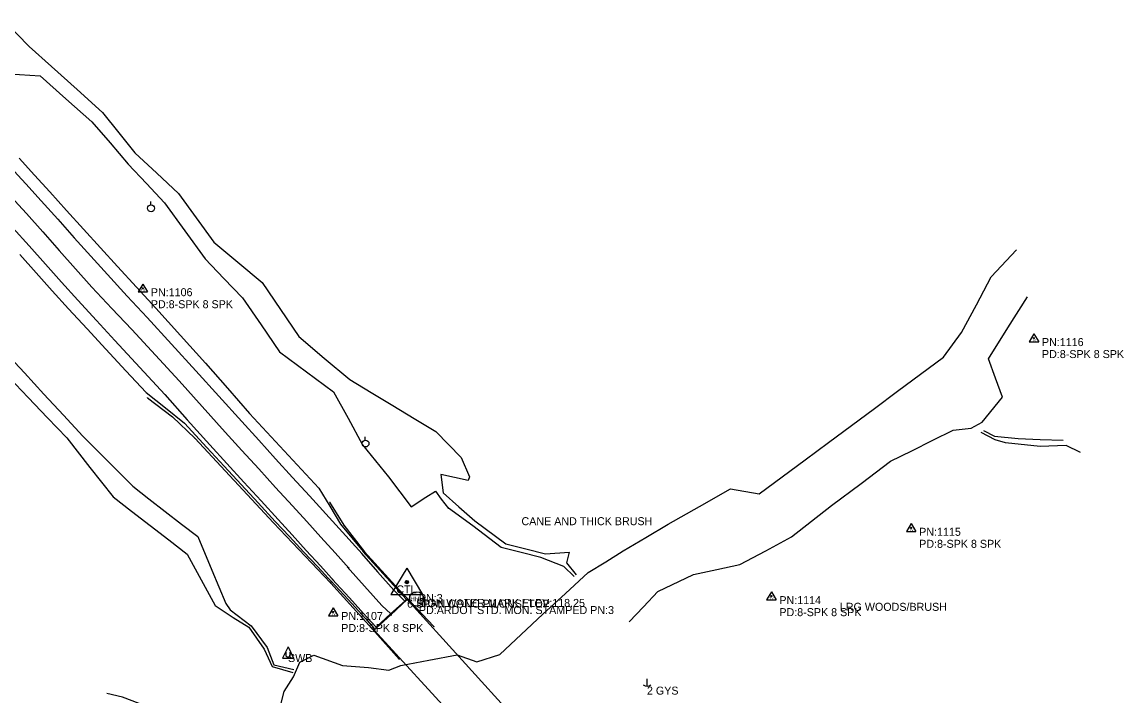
# Model space of a CAD drawing. Extents: x 1193883 to 1197064, y 1474583 to 1477379.
# Drawn here: x 1195271 to 1195959, y 1476046 to 1476468 of the extents above; entities that cross this region are included whole.
import ezdxf

# ---------------------------------------------------------------- set-up
doc = ezdxf.new("R2010")
doc.units = 0
for name, color, linetype in [('S_BRIDGE', 7, 'Continuous'), ('S_BRIDGE_ANNOT', 7, 'Continuous'), ('S_DITCHLINE', 7, 'Continuous'), ('S_EDGE_PAVEMENT', 7, 'Continuous'), ('S_GUARDRAIL', 7, 'Continuous'), ('S_HIST_HIGH_WATER', 7, 'Continuous'), ('S_HIST_HIGH_WATER_ANNOT', 7, 'Continuous'), ('S_MSC_PT_SYM', 7, 'Continuous'), ('S_PAVEMENT_CROWN', 7, 'Continuous'), ('S_PRIMARY_CTL', 7, 'Continuous'), ('S_PRIMARY_CTL_ANNOT', 7, 'Continuous'), ('S_RDW_PT_SYM', 7, 'Continuous'), ('S_SECONDARY_CTL', 7, 'Continuous'), ('S_SECONDARY_CTL_ANNOT', 7, 'Continuous'), ('S_SHOULDER', 7, 'Continuous'), ('S_STR_PT_SYM', 7, 'Continuous'), ('S_STREAM', 7, 'Continuous'), ('S_SURVEY_TEXT_ANNOT', 7, 'Continuous'), ('S_UTILITY_POLE', 7, 'Continuous'), ('S_UTILITY_POLE_ANNOT', 7, 'Continuous')]:
    doc.layers.add(name, color=color, linetype=linetype)

msp = doc.modelspace()

# ---------------------------------------------------------------- linework, layer by layer
at = {"layer": 'S_BRIDGE'}
for p, q in [((1195511.19, 1476106.62), (1195501.07, 1476097.22)), ((1195612.13, 1475995.59), (1195511.19, 1476106.62)), ((1195501.07, 1476097.22), (1195492.02, 1476089.1)), ((1195492.02, 1476089.1), (1195490.61, 1476087.6)), ((1195490.61, 1476087.6), (1195591.91, 1475977.01))]:
    msp.add_line(p, q, dxfattribs=at)
at = {"layer": 'S_DITCHLINE'}
for points in [[(1195260.5, 1476467.51), (1195275.09, 1476452.23), (1195289.07, 1476439.71), (1195305.06, 1476425.33), (1195321.05, 1476410.94), (1195331.13, 1476398.38), (1195341.21, 1476385.82), (1195354.85, 1476373.13), (1195368.49, 1476360.44), (1195379.47, 1476345.25), (1195390.46, 1476330.07), (1195405.56, 1476317.43), (1195420.66, 1476304.79), (1195432.12, 1476287.86), (1195443.59, 1476270.93), (1195459.5, 1476257.55), (1195475.4, 1476244.18), (1195488.82, 1476236.03), (1195502.24, 1476227.88), (1195515.65, 1476219.73), (1195529.07, 1476211.58), (1195544.96, 1476195.49), (1195550.13, 1476183.34), (1195549.41, 1476181.08), (1195532.3, 1476184.81), (1195533.71, 1476173.29), (1195543.57, 1476164.55), (1195553.43, 1476155.8), (1195572.88, 1476141.54), (1195585.26, 1476138.34), (1195597.63, 1476135.14), (1195612.41, 1476136.18), (1195610.83, 1476129.55), (1195616.82, 1476122.09)], [(1195262.66, 1476435.05), (1195281.99, 1476433.98), (1195298.14, 1476419.54), (1195314.28, 1476405.1), (1195325.69, 1476391.95), (1195337.1, 1476378.8), (1195348.38, 1476366.62), (1195359.65, 1476354.44), (1195372.33, 1476336.99), (1195385.02, 1476319.55), (1195396.7, 1476307.36), (1195408.37, 1476295.18), (1195419.99, 1476278.35), (1195431.6, 1476261.52), (1195448.42, 1476249.04), (1195465.24, 1476236.56), (1195474.29, 1476219.9), (1195483.33, 1476203.24), (1195491.42, 1476193.3), (1195499.5, 1476183.36), (1195513.69, 1476164.53), (1195522.92, 1476170.62), (1195528.95, 1476174.39), (1195532.55, 1476169.37), (1195536.98, 1476163.65)], [(1195260, 1476261.4), (1195272.2, 1476248.23), (1195284.39, 1476235.06), (1195296.58, 1476221.89), (1195308.77, 1476208.71), (1195324.3, 1476193.11), (1195339.82, 1476177.5), (1195349.98, 1476169.62), (1195360.14, 1476161.75), (1195370.3, 1476153.87), (1195380.46, 1476146), (1195389.2, 1476125.12), (1195397.93, 1476104.24), (1195400.71, 1476100.33), (1195413.83, 1476090.22), (1195423.81, 1476076.82), (1195427.97, 1476065.92), (1195440.47, 1476062.92)], [(1195262.61, 1476245.42), (1195274.64, 1476232.85), (1195286.67, 1476220.28), (1195298.7, 1476207.71), (1195313.12, 1476189.24), (1195327.54, 1476170.76), (1195339.12, 1476161.84), (1195350.71, 1476152.91), (1195362.3, 1476143.99), (1195373.88, 1476135.06), (1195382.6, 1476118.98), (1195391.32, 1476102.89), (1195402.6, 1476095.53), (1195412.33, 1476089.49), (1195421.83, 1476075.59), (1195426.87, 1476064.94), (1195439.87, 1476061.13)], [(1195931.64, 1476198.62), (1195922.73, 1476202.83), (1195906.47, 1476202.31), (1195884.88, 1476204.67), (1195878.36, 1476206.49), (1195869.72, 1476210.99)], [(1195871.23, 1476212.39), (1195878.03, 1476208.77), (1195892.73, 1476207.2), (1195906.51, 1476206.59), (1195920.83, 1476206.26)], [(1195615.58, 1476120.99), (1195608.97, 1476127.27), (1195594.74, 1476132.9), (1195582.35, 1476136.04), (1195569.96, 1476139.18), (1195552.33, 1476152.82), (1195537.02, 1476163.72)], [(1195426.69, 1476012.38), (1195413.6, 1476014.09), (1195400.5, 1476015.79), (1195386.17, 1476023.45), (1195371.84, 1476031.11), (1195352.65, 1476038.37), (1195333.46, 1476045.64), (1195323.63, 1476048)]]:
    msp.add_lwpolyline(points, dxfattribs=at)
at = {"layer": 'S_EDGE_PAVEMENT'}
for points in [[(1195263.34, 1476376.96), (1195273, 1476366.37), (1195282.65, 1476355.79), (1195293.01, 1476344.26), (1195303.36, 1476332.73), (1195313.72, 1476321.21), (1195324.07, 1476309.68), (1195336.46, 1476296.33), (1195348.85, 1476282.97), (1195364.06, 1476266.25), (1195379.27, 1476249.54), (1195393.62, 1476233.68), (1195407.96, 1476217.82), (1195418.52, 1476206.21), (1195429.08, 1476194.6), (1195439.65, 1476182.99), (1195450.21, 1476171.38), (1195466.66, 1476153.29), (1195483.11, 1476135.19), (1195482.8, 1476135.55), (1195492.81, 1476124.03), (1195502.83, 1476112.51), (1195509.82, 1476105.73)], [(1195264.9, 1476338.85), (1195275.09, 1476327.59), (1195285.28, 1476316.32), (1195295.47, 1476305.05), (1195305.66, 1476293.78), (1195317.19, 1476281.11), (1195328.71, 1476268.43), (1195344.29, 1476251.62), (1195359.86, 1476234.81), (1195373.9, 1476219.06), (1195387.95, 1476203.3), (1195398.62, 1476191.65), (1195409.29, 1476179.99), (1195419.96, 1476168.33), (1195430.63, 1476156.67), (1195439.44, 1476147.02), (1195448.25, 1476137.36), (1195457.06, 1476127.7), (1195465.87, 1476118.04), (1195464.5, 1476119.43), (1195475.21, 1476107.65), (1195485.93, 1476095.87), (1195491.79, 1476089.38), (1195500.93, 1476097.8), (1195510.29, 1476106.14), (1195510.66, 1476106.98)]]:
    msp.add_lwpolyline(points, dxfattribs=at)
at = {"layer": 'S_GUARDRAIL'}
for p, q in [((1195349.13, 1476232.79), (1195364.72, 1476220.84)), ((1195364.72, 1476220.84), (1195378.61, 1476207.43)), ((1195378.61, 1476207.43), (1195427.86, 1476154.58)), ((1195462.8, 1476167.53), (1195471.59, 1476153.23)), ((1195427.86, 1476154.58), (1195463.27, 1476117.11)), ((1195471.59, 1476153.23), (1195484.52, 1476136.58)), ((1195484.52, 1476136.58), (1195506.04, 1476112.91)), ((1195463.27, 1476117.11), (1195463.6, 1476116.83)), ((1195463.6, 1476116.83), (1195489.32, 1476088.36)), ((1195506.04, 1476112.91), (1195527.99, 1476089.74)), ((1195489.32, 1476088.36), (1195506.25, 1476069.37))]:
    msp.add_line(p, q, dxfattribs=at)
at = {"layer": 'S_HIST_HIGH_WATER'}
msp.add_circle((1195517.13, 1476107.06), 4.5, dxfattribs=at)
at = {"layer": 'S_MSC_PT_SYM'}
for points in [[(1195582.61, 1476158.14), (1195582.61, 1476158.19), (1195582.61, 1476158.14), (1195582.56, 1476158.14), (1195582.61, 1476158.14), (1195582.61, 1476158.09), (1195582.61, 1476158.14), (1195582.66, 1476158.14)], [(1195781.45, 1476104.63), (1195781.45, 1476104.68), (1195781.45, 1476104.63), (1195781.4, 1476104.63), (1195781.45, 1476104.63), (1195781.45, 1476104.58), (1195781.45, 1476104.63), (1195781.5, 1476104.63)]]:
    msp.add_lwpolyline(points, dxfattribs=at)
at = {"layer": 'S_PAVEMENT_CROWN'}
msp.add_lwpolyline([(1195263.81, 1476358.54), (1195273.52, 1476347.82), (1195283.73, 1476336.33), (1195293.94, 1476324.85), (1195304.16, 1476313.36), (1195314.37, 1476301.88), (1195326.85, 1476288.62), (1195339.34, 1476275.37), (1195354.06, 1476259.35), (1195368.79, 1476243.33), (1195383.14, 1476227.32), (1195397.48, 1476211.31), (1195408.02, 1476199.79), (1195418.56, 1476188.27), (1195429.1, 1476176.75), (1195439.64, 1476165.23), (1195448.48, 1476155.45), (1195457.33, 1476145.67), (1195466.17, 1476135.88), (1195475.02, 1476126.1), (1195473.67, 1476127.02), (1195484.5, 1476115.01), (1195495.32, 1476102.99), (1195500.97, 1476097.72)], dxfattribs=at)
at = {"layer": 'S_PRIMARY_CTL'}
for p, q in [((1195511.05, 1476126.31), (1195501.01, 1476109.79)), ((1195511.05, 1476126.31), (1195520.87, 1476109.79)), ((1195501.01, 1476109.79), (1195520.87, 1476109.79))]:
    msp.add_line(p, q, dxfattribs=at)
for radius in [1.04, 0.609, 0.344]:
    msp.add_circle((1195511.05, 1476117.61), radius, dxfattribs=at)
at = {"layer": 'S_RDW_PT_SYM'}
for points in [[(1195349.13, 1476232.79), (1195349.13, 1476232.84), (1195349.13, 1476232.79), (1195349.08, 1476232.79), (1195349.13, 1476232.79), (1195349.13, 1476232.74), (1195349.13, 1476232.79), (1195349.18, 1476232.79)], [(1195364.72, 1476220.84), (1195364.72, 1476220.89), (1195364.72, 1476220.84), (1195364.67, 1476220.84), (1195364.72, 1476220.84), (1195364.72, 1476220.79), (1195364.72, 1476220.84), (1195364.77, 1476220.84)], [(1195378.61, 1476207.43), (1195378.61, 1476207.48), (1195378.61, 1476207.43), (1195378.56, 1476207.43), (1195378.61, 1476207.43), (1195378.61, 1476207.38), (1195378.61, 1476207.43), (1195378.66, 1476207.43)], [(1195462.8, 1476167.53), (1195462.8, 1476167.58), (1195462.8, 1476167.53), (1195462.75, 1476167.53), (1195462.8, 1476167.53), (1195462.8, 1476167.48), (1195462.8, 1476167.53), (1195462.85, 1476167.53)], [(1195427.86, 1476154.58), (1195427.86, 1476154.63), (1195427.86, 1476154.58), (1195427.81, 1476154.58), (1195427.86, 1476154.58), (1195427.86, 1476154.53), (1195427.86, 1476154.58), (1195427.91, 1476154.58)], [(1195471.59, 1476153.23), (1195471.59, 1476153.28), (1195471.59, 1476153.23), (1195471.54, 1476153.23), (1195471.59, 1476153.23), (1195471.59, 1476153.18), (1195471.59, 1476153.23), (1195471.64, 1476153.23)], [(1195484.52, 1476136.58), (1195484.52, 1476136.63), (1195484.52, 1476136.58), (1195484.47, 1476136.58), (1195484.52, 1476136.58), (1195484.52, 1476136.53), (1195484.52, 1476136.58), (1195484.57, 1476136.58)], [(1195463.27, 1476117.11), (1195463.27, 1476117.16), (1195463.27, 1476117.11), (1195463.22, 1476117.11), (1195463.27, 1476117.11), (1195463.27, 1476117.06), (1195463.27, 1476117.11), (1195463.32, 1476117.11)], [(1195463.6, 1476116.83), (1195463.6, 1476116.88), (1195463.6, 1476116.83), (1195463.55, 1476116.83), (1195463.6, 1476116.83), (1195463.6, 1476116.78), (1195463.6, 1476116.83), (1195463.65, 1476116.83)], [(1195506.04, 1476112.91), (1195506.04, 1476112.96), (1195506.04, 1476112.91), (1195505.99, 1476112.91), (1195506.04, 1476112.91), (1195506.04, 1476112.86), (1195506.04, 1476112.91), (1195506.09, 1476112.91)], [(1195527.99, 1476089.74), (1195527.99, 1476089.79), (1195527.99, 1476089.74), (1195527.94, 1476089.74), (1195527.99, 1476089.74), (1195527.99, 1476089.69), (1195527.99, 1476089.74), (1195528.04, 1476089.74)], [(1195489.32, 1476088.36), (1195489.32, 1476088.41), (1195489.32, 1476088.36), (1195489.27, 1476088.36), (1195489.32, 1476088.36), (1195489.32, 1476088.31), (1195489.32, 1476088.36), (1195489.37, 1476088.36)], [(1195506.25, 1476069.37), (1195506.25, 1476069.42), (1195506.25, 1476069.37), (1195506.2, 1476069.37), (1195506.25, 1476069.37), (1195506.25, 1476069.32), (1195506.25, 1476069.37), (1195506.3, 1476069.37)]]:
    msp.add_lwpolyline(points, dxfattribs=at)
at = {"layer": 'S_SECONDARY_CTL'}
for p, q in [((1195346.16, 1476303.81), (1195343.15, 1476298.86)), ((1195346.16, 1476303.81), (1195349.1, 1476298.86)), ((1195343.15, 1476298.86), (1195349.1, 1476298.86)), ((1195902.65, 1476272.66), (1195899.64, 1476267.71)), ((1195902.65, 1476272.66), (1195905.6, 1476267.71)), ((1195899.64, 1476267.71), (1195905.6, 1476267.71)), ((1195825.99, 1476154.11), (1195822.98, 1476149.16)), ((1195825.99, 1476154.11), (1195828.94, 1476149.16)), ((1195822.98, 1476149.16), (1195828.94, 1476149.16)), ((1195738.66, 1476111.41), (1195735.65, 1476106.46)), ((1195738.66, 1476111.41), (1195741.6, 1476106.46)), ((1195735.65, 1476106.46), (1195741.6, 1476106.46)), ((1195465.06, 1476101.53), (1195462.05, 1476096.58)), ((1195462.05, 1476096.58), (1195468.01, 1476096.58)), ((1195465.06, 1476101.53), (1195468.01, 1476096.58))]:
    msp.add_line(p, q, dxfattribs=at)
for centre, radius in [((1195346.16, 1476301.2), 0.311), ((1195346.16, 1476301.2), 0.183), ((1195346.16, 1476301.2), 0.103), ((1195902.65, 1476270.05), 0.311), ((1195902.65, 1476270.05), 0.183), ((1195902.65, 1476270.05), 0.103), ((1195825.99, 1476151.5), 0.311), ((1195825.99, 1476151.5), 0.183), ((1195825.99, 1476151.5), 0.103), ((1195738.66, 1476108.8), 0.311), ((1195738.66, 1476108.8), 0.183), ((1195738.66, 1476108.8), 0.103), ((1195465.06, 1476098.92), 0.311), ((1195465.06, 1476098.92), 0.183), ((1195465.06, 1476098.92), 0.103)]:
    msp.add_circle(centre, radius, dxfattribs=at)
at = {"layer": 'S_SHOULDER'}
for points in [[(1195269, 1476382.46), (1195278.5, 1476371.91), (1195287.99, 1476361.36), (1195298.56, 1476349.69), (1195309.13, 1476338.02), (1195319.7, 1476326.35), (1195330.27, 1476314.68), (1195342.25, 1476301.75), (1195354.23, 1476288.82), (1195369.72, 1476271.58), (1195385.21, 1476254.35), (1195399.04, 1476238.65), (1195412.87, 1476222.96), (1195423.68, 1476211.28), (1195434.49, 1476199.61), (1195445.29, 1476187.94), (1195456.1, 1476176.27), (1195462.9, 1476164.99), (1195469.69, 1476153.7), (1195483.71, 1476136.63), (1195483.54, 1476136.7), (1195494.18, 1476125.04), (1195504.83, 1476113.38), (1195510.67, 1476107.02)], [(1195269.41, 1476322.17), (1195279.49, 1476310.91), (1195289.58, 1476299.66), (1195299.66, 1476288.4), (1195311.31, 1476275.8), (1195322.97, 1476263.2), (1195335.62, 1476249.67), (1195348.28, 1476236.14), (1195360.27, 1476226.48), (1195372.26, 1476216.81), (1195386.2, 1476201.65), (1195396.85, 1476190.11), (1195407.51, 1476178.56), (1195418.16, 1476167.01), (1195428.82, 1476155.46), (1195437.66, 1476145.99), (1195446.51, 1476136.53), (1195455.36, 1476127.07), (1195464.2, 1476117.6), (1195463.53, 1476118.47), (1195474.33, 1476106.7), (1195485.13, 1476094.92), (1195490.34, 1476088.72), (1195490.13, 1476088.15)]]:
    msp.add_lwpolyline(points, dxfattribs=at)
at = {"layer": 'S_STR_PT_SYM'}
for points in [[(1195511.19, 1476106.62), (1195511.19, 1476107.12), (1195511.19, 1476106.62), (1195510.69, 1476106.62), (1195511.19, 1476106.62), (1195511.19, 1476106.12), (1195511.19, 1476106.62), (1195511.69, 1476106.62)], [(1195501.07, 1476097.22), (1195501.07, 1476097.72), (1195501.07, 1476097.22), (1195500.57, 1476097.22), (1195501.07, 1476097.22), (1195501.07, 1476096.72), (1195501.07, 1476097.22), (1195501.57, 1476097.22)], [(1195492.02, 1476089.1), (1195492.02, 1476089.6), (1195492.02, 1476089.1), (1195491.52, 1476089.1), (1195492.02, 1476089.1), (1195492.02, 1476088.6), (1195492.02, 1476089.1), (1195492.52, 1476089.1)], [(1195490.61, 1476087.6), (1195490.61, 1476088.1), (1195490.61, 1476087.6), (1195490.11, 1476087.6), (1195490.61, 1476087.6), (1195490.61, 1476087.1), (1195490.61, 1476087.6), (1195491.11, 1476087.6)]]:
    msp.add_lwpolyline(points, dxfattribs=at)
at = {"layer": 'S_STREAM'}
for points in [[(1195430.29, 1476032.71), (1195434.43, 1476049.16), (1195440.17, 1476058.47), (1195444.17, 1476067.47), (1195453, 1476071.97), (1195470.87, 1476065.45), (1195487.03, 1476064.25), (1195499.73, 1476062.6), (1195507.2, 1476065.43), (1195524.8, 1476068.8), (1195542.39, 1476072.17), (1195554.68, 1476067.71), (1195569.01, 1476072.39), (1195582.45, 1476084.92), (1195595.9, 1476097.46), (1195610.1, 1476110.52), (1195624.31, 1476123.59), (1195635.25, 1476130.31), (1195646.2, 1476137.02), (1195660.24, 1476145.35), (1195674.29, 1476153.68), (1195693.75, 1476164.75), (1195713.2, 1476175.81), (1195731.13, 1476172.7), (1195745.51, 1476183.38), (1195759.88, 1476194.06), (1195774.26, 1476204.74), (1195788.63, 1476215.42), (1195803.01, 1476226.1), (1195817.39, 1476236.78), (1195831.76, 1476247.46), (1195846.14, 1476258.14), (1195857.51, 1476273.46), (1195866.71, 1476290.9), (1195875.92, 1476308.34), (1195891.84, 1476325.22)], [(1195649.91, 1476092.7), (1195658.84, 1476102.2), (1195667.78, 1476111.7), (1195690.09, 1476122.26), (1195704.59, 1476125.39), (1195719.08, 1476128.52), (1195735.12, 1476137.18), (1195751.16, 1476145.84), (1195763.65, 1476155.64), (1195776.13, 1476165.45), (1195794.65, 1476179.26), (1195813.17, 1476193.08), (1195826.37, 1476199.62), (1195839.57, 1476206.16), (1195852.29, 1476212.53), (1195863.49, 1476213.86), (1195870.4, 1476217.45), (1195882.92, 1476233.11), (1195878.56, 1476245.05), (1195874.21, 1476256.99), (1195886.44, 1476276.4), (1195898.66, 1476295.81)]]:
    msp.add_lwpolyline(points, dxfattribs=at)
at = {"layer": 'S_UTILITY_POLE'}
for p, q in [((1195351.19, 1476353.28), (1195351.19, 1476355.38)), ((1195485.1, 1476206.27), (1195485.1, 1476208.38)), ((1195436.83, 1476077.21), (1195433.3, 1476070.12)), ((1195436.83, 1476077.21), (1195440.32, 1476070.12)), ((1195433.3, 1476070.12), (1195440.32, 1476070.12)), ((1195435.63, 1476071.36), (1195435.63, 1476073.8)), ((1195436.25, 1476070.7), (1195435.63, 1476071.36)), ((1195437.45, 1476070.7), (1195436.25, 1476070.7)), ((1195437.99, 1476071.36), (1195437.45, 1476070.7)), ((1195437.99, 1476073.8), (1195437.99, 1476071.36)), ((1195660.96, 1476057.22), (1195660.96, 1476052.5))]:
    msp.add_line(p, q, dxfattribs=at)
for centre in [(1195351.31, 1476351.13), (1195485.23, 1476204.13)]:
    msp.add_circle(centre, 2.13, dxfattribs=at)
msp.add_arc((1195661.02, 1476055.92), 3.41, 226.39718, 313.60282, dxfattribs=at)

# ---------------------------------------------------------------- texts
at = {"layer": 'S_BRIDGE_ANNOT'}
msp.add_text('6 SPAN CONC PILONS/ TOP', height=5, dxfattribs=at).set_placement((1195511.19, 1476101.62))
at = {"layer": 'S_HIST_HIGH_WATER'}
msp.add_text('HHW', height=3, rotation=360, dxfattribs=at).set_placement((1195513.05, 1476105.56))
at = {"layer": 'S_HIST_HIGH_WATER_ANNOT'}
msp.add_text('HIGH WATER MARK ELEV:118.25', height=5, dxfattribs=at).set_placement((1195517.13, 1476102.06))
at = {"layer": 'S_PRIMARY_CTL'}
msp.add_text('CTL', height=5, rotation=360, dxfattribs=at).set_placement((1195504.46, 1476110.53))
at = {"layer": 'S_PRIMARY_CTL_ANNOT'}
for s, p in [('PN:3', (1195518.55, 1476105.11)), ('PD:ARDOT STD. MON. STAMPED PN:3', (1195518.55, 1476097.61))]:
    msp.add_text(s, height=5, dxfattribs=at).set_placement(p)
at = {"layer": 'S_SECONDARY_CTL'}
for p in [(1195344.95, 1476299.19), (1195901.45, 1476268.04), (1195824.79, 1476149.49), (1195737.45, 1476106.79), (1195463.86, 1476096.91)]:
    msp.add_text('TV', height=1.5, rotation=360, dxfattribs=at).set_placement(p)
at = {"layer": 'S_SECONDARY_CTL_ANNOT'}
for s, p in [('PN:1106', (1195351.16, 1476296.2)), ('PD:8-SPK 8 SPK', (1195351.16, 1476288.7)), ('PN:1116', (1195907.65, 1476265.05)), ('PD:8-SPK 8 SPK', (1195907.65, 1476257.55)), ('PN:1115', (1195830.99, 1476146.5)), ('PD:8-SPK 8 SPK', (1195830.99, 1476139)), ('PN:1114', (1195743.66, 1476103.8)), ('PN:1107', (1195470.06, 1476093.92)), ('PD:8-SPK 8 SPK', (1195743.66, 1476096.3)), ('PD:8-SPK 8 SPK', (1195470.06, 1476086.42))]:
    msp.add_text(s, height=5, dxfattribs=at).set_placement(p)
at = {"layer": 'S_SURVEY_TEXT_ANNOT'}
for s, p in [('CANE AND THICK BRUSH', (1195582.61, 1476153.14)), ('LRG WOODS/BRUSH', (1195781.45, 1476099.63))]:
    msp.add_text(s, height=5, dxfattribs=at).set_placement(p)
at = {"layer": 'S_UTILITY_POLE_ANNOT'}
for s, p in [('SWB', (1195436.83, 1476067.67)), ('2 GYS', (1195660.98, 1476047.28))]:
    msp.add_text(s, height=5, dxfattribs=at).set_placement(p)

doc.saveas('drawing.dxf')
